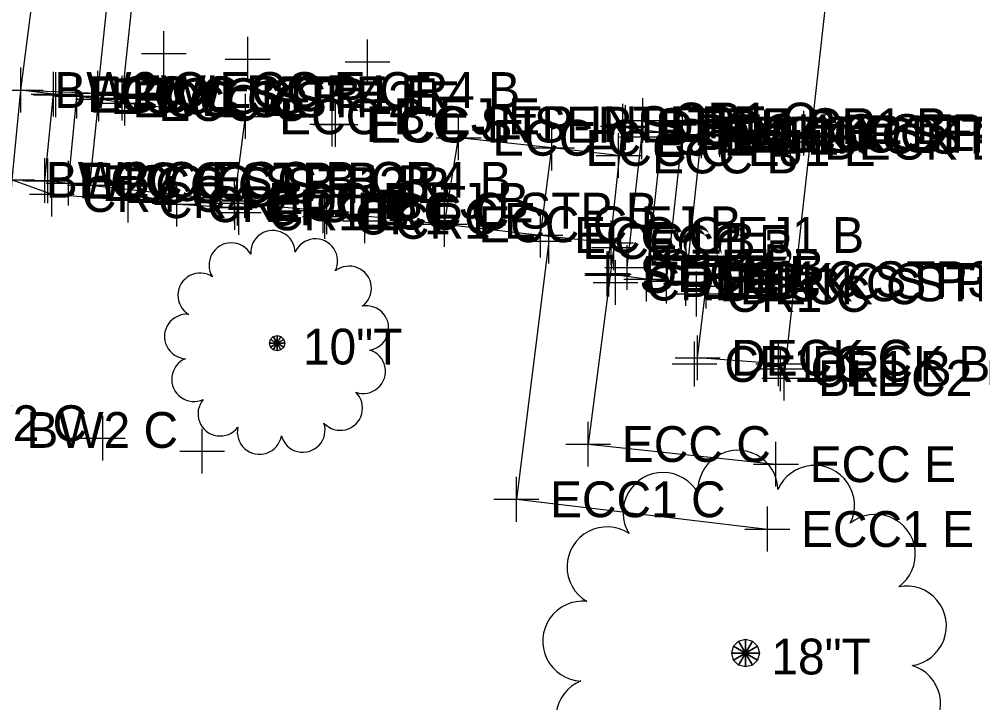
# Model space of a CAD drawing. Extents: x 1363693 to 1365209, y 422201 to 424153.
# Drawn here: x 1364291.51 to 1364334.2, y 423273.43 to 423303.98 of the extents above; entities that cross this region are included whole.
import ezdxf

# ---------------------------------------------------------------- set-up
doc = ezdxf.new("R2010")
doc.units = 0
for name, color, linetype in [('BD_X_Building', 7, 'Continuous'), ('O-ALGN-BASELINE-WERK-CL-RW', 7, 'Continuous'), ('O-ALGN-TEXT-BASELINE-WERK-CL-RW', 7, 'Continuous'), ('OWNERS', 7, 'Continuous'), ('PV_X_Driveway', 7, 'Continuous'), ('PV_X_Joint', 7, 'Continuous'), ('RD_X_Misc_Items', 7, 'Continuous'), ('RD_X_Wall', 7, 'Continuous'), ('SV_X_Original_Ground', 7, 'Continuous'), ('SV_X_Random_Point', 7, 'Continuous'), ('SV_X_Shot_Marker', 7, 'Continuous'), ('VG_X_Cells', 7, 'Continuous'), ('VG_X_Text', 7, 'Continuous')]:
    doc.layers.add(name, color=color, linetype=linetype)

msp = doc.modelspace()

# ---------------------------------------------------------------- linework, layer by layer
at = {"layer": 'BD_X_Building'}
for p, q in [((1364325.684, 423287.942), (1364329.652, 423323.832)), ((1364295.029, 423300.671), (1364295.921, 423309.372)), ((1364296.116, 423300.448), (1364296.997, 423308.883))]:
    msp.add_line(p, q, dxfattribs=at)
at = {"layer": 'O-ALGN-BASELINE-WERK-CL-RW'}
msp.add_line((1364291.58, 423300.813), (1364295.029, 423300.671), dxfattribs=at)
msp.add_lwpolyline([(1364291.2, 423296.798), (1364292.969, 423296.164), (1364296.376, 423295.889), (1364298.558, 423295.71), (1364301.138, 423295.56)], dxfattribs=at)
at = {"layer": 'O-ALGN-TEXT-BASELINE-WERK-CL-RW'}
msp.add_lwpolyline([(1364288.049, 423260.634), (1364290.333, 423285.623), (1364291.2, 423296.798), (1364291.58, 423300.813), (1364292.823, 423310.443), (1364293.111, 423313.713), (1364294.382, 423326.121), (1364294.901, 423331.286), (1364295.277, 423335.321), (1364295.682, 423341.235), (1364297.432, 423360.37), (1364299.6, 423383.973), (1364299.789, 423385.241), (1364300.506, 423393.275), (1364302.133, 423410.038), (1364303.056, 423419.974), (1364303.785, 423425.594), (1364316.813, 423424.472), (1364342.217, 423421.511), (1364361.421, 423419.342)], dxfattribs=at)
at = {"layer": 'OWNERS'}
for p, q in [((1364292.654, 423296.77), (1364293.04, 423300.624)), ((1364293.709, 423296.649), (1364294.082, 423300.539)), ((1364294.665, 423296.563), (1364295.07, 423300.4))]:
    msp.add_line(p, q, dxfattribs=at)
for points in [[(1364301.62, 423299.637), (1364296.233, 423300.231), (1364295.07, 423300.4), (1364294.082, 423300.539), (1364293.154, 423300.605), (1364293.04, 423300.624), (1364291.58, 423300.813)], [(1364291.2, 423296.798), (1364292.654, 423296.77), (1364292.794, 423296.756), (1364293.709, 423296.649), (1364294.665, 423296.563), (1364301.134, 423295.864)]]:
    msp.add_lwpolyline(points, dxfattribs=at)
at = {"layer": 'PV_X_Driveway'}
for p, q in [((1364292.654, 423296.77), (1364293.04, 423300.624)), ((1364293.709, 423296.649), (1364294.082, 423300.539)), ((1364294.665, 423296.563), (1364295.07, 423300.4)), ((1364317.776, 423292.62), (1364318.479, 423299.197)), ((1364318.669, 423292.884), (1364319.322, 423298.718)), ((1364319.523, 423292.359), (1364320.249, 423298.933)), ((1364320.42, 423292.279), (1364321.131, 423298.819)), ((1364321.287, 423292.173), (1364321.979, 423298.769))]:
    msp.add_line(p, q, dxfattribs=at)
for points in [[(1364301.62, 423299.637), (1364296.233, 423300.231), (1364295.07, 423300.4), (1364294.082, 423300.539), (1364293.154, 423300.605), (1364293.04, 423300.624), (1364291.58, 423300.813)], [(1364318.274, 423297.887), (1364315.306, 423298.224), (1364311.139, 423298.678)], [(1364291.2, 423296.798), (1364292.654, 423296.77), (1364292.794, 423296.756), (1364293.709, 423296.649), (1364294.665, 423296.563), (1364301.134, 423295.864)], [(1364301.264, 423295.76), (1364305.092, 423295.423), (1364305.25, 423295.375), (1364310.514, 423294.813), (1364314.788, 423294.332), (1364317.944, 423293.983)], [(1364315.169, 423294.065), (1364313.716, 423282.525), (1364324.927, 423281.197)], [(1364318.074, 423293.771), (1364316.926, 423284.993), (1364325.312, 423284.093)]]:
    msp.add_lwpolyline(points, dxfattribs=at)
at = {"layer": 'PV_X_Joint'}
for p, q in [((1364301.134, 423295.864), (1364301.62, 423299.637)), ((1364310.514, 423294.813), (1364311.139, 423298.678)), ((1364314.788, 423294.332), (1364315.306, 423298.224))]:
    msp.add_line(p, q, dxfattribs=at)
at = {"layer": 'RD_X_Misc_Items'}
for p, q in [((1364318.586, 423299.142), (1364320.249, 423298.933)), ((1364320.249, 423298.933), (1364321.131, 423298.819)), ((1364321.131, 423298.819), (1364321.979, 423298.769)), ((1364321.979, 423298.769), (1364322.808, 423298.825)), ((1364322.808, 423298.825), (1364325.966, 423298.503)), ((1364319.523, 423292.359), (1364317.85, 423292.592)), ((1364320.42, 423292.279), (1364319.523, 423292.359)), ((1364321.287, 423292.173), (1364320.42, 423292.279)), ((1364322.187, 423292.044), (1364321.287, 423292.173)), ((1364321.813, 423288.85), (1364322.187, 423292.044)), ((1364325.419, 423288.579), (1364321.813, 423288.85))]:
    msp.add_line(p, q, dxfattribs=at)
at = {"layer": 'RD_X_Wall'}
for p, q in [((1364295.029, 423300.671), (1364295.921, 423309.372)), ((1364296.116, 423300.448), (1364296.997, 423308.883))]:
    msp.add_line(p, q, dxfattribs=at)
at = {"layer": 'SV_X_Original_Ground'}
for p, q in [((1364297.97, 423301.442), (1364297.97, 423303.442)), ((1364301.717, 423301.192), (1364301.717, 423303.192)), ((1364307.069, 423301.071), (1364307.069, 423303.071)), ((1364296.97, 423302.442), (1364298.97, 423302.442)), ((1364300.717, 423302.192), (1364302.717, 423302.192)), ((1364306.069, 423302.071), (1364308.069, 423302.071)), ((1364319.362, 423298.448), (1364319.362, 423300.448)), ((1364318.586, 423298.142), (1364318.586, 423300.142)), ((1364320.249, 423297.933), (1364320.249, 423299.933)), ((1364321.131, 423297.819), (1364321.131, 423299.819)), ((1364322.808, 423297.825), (1364322.808, 423299.825)), ((1364326.553, 423297.888), (1364326.553, 423299.888)), ((1364318.362, 423299.448), (1364320.362, 423299.448)), ((1364319.322, 423297.718), (1364319.322, 423299.718)), ((1364321.979, 423297.769), (1364321.979, 423299.769)), ((1364325.966, 423297.503), (1364325.966, 423299.503)), ((1364317.586, 423299.142), (1364319.586, 423299.142)), ((1364318.322, 423298.718), (1364320.322, 423298.718)), ((1364319.249, 423298.933), (1364321.249, 423298.933)), ((1364320.131, 423298.819), (1364322.131, 423298.819)), ((1364320.979, 423298.769), (1364322.979, 423298.769)), ((1364321.808, 423298.825), (1364323.808, 423298.825)), ((1364325.553, 423298.888), (1364327.553, 423298.888)), ((1364324.966, 423298.503), (1364326.966, 423298.503)), ((1364292.969, 423295.164), (1364292.969, 423297.164)), ((1364296.376, 423294.889), (1364296.376, 423296.889)), ((1364298.558, 423294.71), (1364298.558, 423296.71)), ((1364301.138, 423294.56), (1364301.138, 423296.56)), ((1364291.969, 423296.164), (1364293.969, 423296.164)), ((1364301.319, 423294.344), (1364301.319, 423296.344)), ((1364305.166, 423294.158), (1364305.166, 423296.158)), ((1364306.95, 423293.964), (1364306.95, 423295.964)), ((1364295.376, 423295.889), (1364297.376, 423295.889)), ((1364297.558, 423295.71), (1364299.558, 423295.71)), ((1364300.138, 423295.56), (1364302.138, 423295.56)), ((1364300.319, 423295.344), (1364302.319, 423295.344)), ((1364304.166, 423295.158), (1364306.166, 423295.158)), ((1364305.95, 423294.964), (1364307.95, 423294.964)), ((1364318.669, 423291.884), (1364318.669, 423293.884)), ((1364317.85, 423291.592), (1364317.85, 423293.592)), ((1364318.141, 423291.209), (1364318.141, 423293.209)), ((1364319.523, 423291.359), (1364319.523, 423293.359)), ((1364320.42, 423291.279), (1364320.42, 423293.279)), ((1364321.287, 423291.173), (1364321.287, 423293.173)), ((1364322.187, 423291.044), (1364322.187, 423293.044)), ((1364316.85, 423292.592), (1364318.85, 423292.592)), ((1364317.669, 423292.884), (1364319.669, 423292.884)), ((1364321.764, 423290.7), (1364321.764, 423292.7)), ((1364317.141, 423292.209), (1364319.141, 423292.209)), ((1364318.523, 423292.359), (1364320.523, 423292.359)), ((1364319.42, 423292.279), (1364321.42, 423292.279)), ((1364320.287, 423292.173), (1364322.287, 423292.173)), ((1364320.764, 423291.7), (1364322.764, 423291.7)), ((1364321.187, 423292.044), (1364323.187, 423292.044)), ((1364321.668, 423287.571), (1364321.668, 423289.571)), ((1364321.813, 423287.85), (1364321.813, 423289.85)), ((1364325.419, 423287.579), (1364325.419, 423289.579)), ((1364325.52, 423287.352), (1364325.52, 423289.352)), ((1364320.813, 423288.85), (1364322.813, 423288.85)), ((1364320.668, 423288.571), (1364322.668, 423288.571)), ((1364324.419, 423288.579), (1364326.419, 423288.579)), ((1364324.52, 423288.352), (1364326.52, 423288.352)), ((1364295.249, 423284.261), (1364295.249, 423286.261)), ((1364299.685, 423283.676), (1364299.685, 423285.676)), ((1364294.249, 423285.261), (1364296.249, 423285.261)), ((1364298.685, 423284.676), (1364300.685, 423284.676))]:
    msp.add_line(p, q, dxfattribs=at)
at = {"layer": 'SV_X_Random_Point'}
for p, q in [((1364295.029, 423299.671), (1364295.029, 423301.671)), ((1364296.116, 423299.448), (1364296.116, 423301.448)), ((1364294.029, 423300.671), (1364296.029, 423300.671)), ((1364295.116, 423300.448), (1364297.116, 423300.448)), ((1364318.479, 423298.197), (1364318.479, 423300.197)), ((1364317.479, 423299.197), (1364319.479, 423299.197)), ((1364317.776, 423291.62), (1364317.776, 423293.62)), ((1364317.78, 423291.545), (1364317.78, 423293.545)), ((1364316.776, 423292.62), (1364318.776, 423292.62)), ((1364316.78, 423292.545), (1364318.78, 423292.545))]:
    msp.add_line(p, q, dxfattribs=at)
at = {"layer": 'SV_X_Shot_Marker'}
for p, q in [((1364291.58, 423299.813), (1364291.58, 423301.813)), ((1364293.04, 423299.624), (1364293.04, 423301.624)), ((1364293.154, 423299.605), (1364293.154, 423301.605)), ((1364294.082, 423299.539), (1364294.082, 423301.539)), ((1364295.07, 423299.4), (1364295.07, 423301.4)), ((1364296.233, 423299.231), (1364296.233, 423301.231)), ((1364290.58, 423300.813), (1364292.58, 423300.813)), ((1364292.04, 423300.624), (1364294.04, 423300.624)), ((1364292.154, 423300.605), (1364294.154, 423300.605)), ((1364293.082, 423300.539), (1364295.082, 423300.539)), ((1364294.07, 423300.4), (1364296.07, 423300.4)), ((1364295.233, 423300.231), (1364297.233, 423300.231)), ((1364301.62, 423298.637), (1364301.62, 423300.637)), ((1364305.493, 423298.289), (1364305.493, 423300.289)), ((1364305.634, 423298.268), (1364305.634, 423300.268)), ((1364300.62, 423299.637), (1364302.62, 423299.637)), ((1364311.139, 423297.678), (1364311.139, 423299.678)), ((1364304.493, 423299.289), (1364306.493, 423299.289)), ((1364304.634, 423299.268), (1364306.634, 423299.268)), ((1364315.306, 423297.224), (1364315.306, 423299.224)), ((1364310.139, 423298.678), (1364312.139, 423298.678)), ((1364318.274, 423296.887), (1364318.274, 423298.887)), ((1364314.306, 423298.224), (1364316.306, 423298.224)), ((1364292.654, 423295.77), (1364292.654, 423297.77)), ((1364292.794, 423295.756), (1364292.794, 423297.756)), ((1364317.274, 423297.887), (1364319.274, 423297.887)), ((1364293.709, 423295.649), (1364293.709, 423297.649)), ((1364294.665, 423295.563), (1364294.665, 423297.563)), ((1364301.134, 423294.864), (1364301.134, 423296.864)), ((1364290.2, 423296.798), (1364292.2, 423296.798)), ((1364291.654, 423296.77), (1364293.654, 423296.77)), ((1364291.794, 423296.756), (1364293.794, 423296.756)), ((1364292.709, 423296.649), (1364294.709, 423296.649)), ((1364293.665, 423296.563), (1364295.665, 423296.563)), ((1364301.264, 423294.76), (1364301.264, 423296.76)), ((1364305.092, 423294.423), (1364305.092, 423296.423)), ((1364305.25, 423294.375), (1364305.25, 423296.375)), ((1364300.134, 423295.864), (1364302.134, 423295.864)), ((1364300.264, 423295.76), (1364302.264, 423295.76)), ((1364310.514, 423293.813), (1364310.514, 423295.813)), ((1364304.092, 423295.423), (1364306.092, 423295.423)), ((1364304.25, 423295.375), (1364306.25, 423295.375)), ((1364314.788, 423293.332), (1364314.788, 423295.332)), ((1364309.514, 423294.813), (1364311.514, 423294.813)), ((1364315.169, 423293.065), (1364315.169, 423295.065)), ((1364317.944, 423292.983), (1364317.944, 423294.983)), ((1364318.074, 423292.771), (1364318.074, 423294.771)), ((1364313.788, 423294.332), (1364315.788, 423294.332)), ((1364314.169, 423294.065), (1364316.169, 423294.065)), ((1364316.944, 423293.983), (1364318.944, 423293.983)), ((1364317.074, 423293.771), (1364319.074, 423293.771)), ((1364325.684, 423286.942), (1364325.684, 423288.942)), ((1364324.684, 423287.942), (1364326.684, 423287.942)), ((1364316.926, 423283.993), (1364316.926, 423285.993)), ((1364315.926, 423284.993), (1364317.926, 423284.993)), ((1364325.312, 423283.093), (1364325.312, 423285.093)), ((1364324.312, 423284.093), (1364326.312, 423284.093)), ((1364313.716, 423281.525), (1364313.716, 423283.525)), ((1364312.716, 423282.525), (1364314.716, 423282.525)), ((1364324.927, 423280.197), (1364324.927, 423282.197)), ((1364323.927, 423281.197), (1364325.927, 423281.197))]:
    msp.add_line(p, q, dxfattribs=at)
at = {"layer": 'VG_X_Cells'}
for points in [[(1364302.732, 423289.672), (1364303.029, 423289.5), (1364303.029, 423289.5), (1364302.686, 423289.5)], [(1364302.857, 423289.797), (1364303.029, 423289.5), (1364303.029, 423289.5), (1364302.732, 423289.672)], [(1364303.029, 423289.843), (1364303.029, 423289.5), (1364303.029, 423289.5), (1364302.857, 423289.797)], [(1364303.201, 423289.797), (1364303.029, 423289.5), (1364303.029, 423289.5), (1364303.029, 423289.843)], [(1364303.326, 423289.672), (1364303.029, 423289.5), (1364303.029, 423289.5), (1364303.201, 423289.797)], [(1364303.372, 423289.5), (1364303.029, 423289.5), (1364303.029, 423289.5), (1364303.326, 423289.672)], [(1364302.686, 423289.5), (1364303.029, 423289.5), (1364303.029, 423289.5), (1364302.732, 423289.328)], [(1364302.732, 423289.328), (1364303.029, 423289.5), (1364303.029, 423289.5), (1364302.857, 423289.203)], [(1364302.857, 423289.203), (1364303.029, 423289.5), (1364303.029, 423289.5), (1364303.029, 423289.157)], [(1364303.029, 423289.157), (1364303.029, 423289.5), (1364303.029, 423289.5), (1364303.201, 423289.203)], [(1364303.201, 423289.203), (1364303.029, 423289.5), (1364303.029, 423289.5), (1364303.326, 423289.328)], [(1364303.326, 423289.328), (1364303.029, 423289.5), (1364303.029, 423289.5), (1364303.372, 423289.5)], [(1364323.416, 423275.959), (1364323.951, 423275.65), (1364323.951, 423275.65), (1364323.333, 423275.65)], [(1364323.642, 423276.185), (1364323.951, 423275.65), (1364323.951, 423275.65), (1364323.416, 423275.959)], [(1364323.951, 423276.268), (1364323.951, 423275.65), (1364323.951, 423275.65), (1364323.642, 423276.185)], [(1364324.26, 423276.185), (1364323.951, 423275.65), (1364323.951, 423275.65), (1364323.951, 423276.268)], [(1364324.486, 423275.959), (1364323.951, 423275.65), (1364323.951, 423275.65), (1364324.26, 423276.185)], [(1364324.569, 423275.65), (1364323.951, 423275.65), (1364323.951, 423275.65), (1364324.486, 423275.959)], [(1364323.333, 423275.65), (1364323.951, 423275.65), (1364323.951, 423275.65), (1364323.416, 423275.341)], [(1364323.416, 423275.341), (1364323.951, 423275.65), (1364323.951, 423275.65), (1364323.642, 423275.115)], [(1364323.642, 423275.115), (1364323.951, 423275.65), (1364323.951, 423275.65), (1364323.951, 423275.032)], [(1364323.951, 423275.032), (1364323.951, 423275.65), (1364323.951, 423275.65), (1364324.26, 423275.115)], [(1364324.26, 423275.115), (1364323.951, 423275.65), (1364323.951, 423275.65), (1364324.486, 423275.341)], [(1364324.486, 423275.341), (1364323.951, 423275.65), (1364323.951, 423275.65), (1364324.569, 423275.65)]]:
    msp.add_lwpolyline(points, close=True, dxfattribs=at)
for centre, radius, start, end in [((1364302.84, 423293.544), 0.992, 1.241, 184.1237), ((1364300.982, 423292.993), 0.992, 28.9333, 211.816), ((1364304.741, 423293.169), 0.992, 333.5487, 156.4314), ((1364299.593, 423291.641), 0.992, 56.6256, 239.5083), ((1364306.25, 423291.953), 0.992, 305.8564, 128.7391), ((1364307.021, 423290.176), 0.992, 278.1641, 101.0468), ((1364298.992, 423289.799), 0.992, 84.3179, 267.2006), ((1364306.877, 423288.243), 0.992, 250.4718, 73.3545), ((1364299.315, 423287.889), 0.992, 112.0103, 294.8929), ((1364300.489, 423286.347), 0.992, 139.7026, 322.5852), ((1364305.853, 423286.599), 0.992, 222.7795, 45.6622), ((1364302.245, 423285.528), 0.992, 167.3949, 350.2776), ((1364304.181, 423285.619), 0.992, 195.0872, 17.9699), ((1364323.61, 423282.929), 1.786, 1.241, 184.1237), ((1364327.032, 423282.254), 1.786, 333.5487, 156.4314), ((1364320.266, 423281.937), 1.786, 28.9333, 211.816), ((1364329.748, 423280.066), 1.786, 305.8564, 128.7391), ((1364317.767, 423279.504), 1.786, 56.6256, 239.5083), ((1364331.136, 423276.866), 1.786, 278.1641, 101.0468), ((1364316.684, 423276.189), 1.786, 84.3179, 267.2006), ((1364330.878, 423273.388), 1.786, 250.4718, 73.3545), ((1364317.266, 423272.75), 1.786, 112.0103, 294.8929)]:
    msp.add_arc(centre, radius, start, end, dxfattribs=at)

# ---------------------------------------------------------------- texts
at = {"layer": 'SV_X_Original_Ground'}
for s, p in [('CR1 C', (1364320.699, 423298.648)), ('DECK B', (1364320.086, 423298.342)), ('STP4 E', (1364320.761, 423297.918)), ('DECK C STP3 E', (1364321.749, 423298.133)), ('DECK C STP2 E', (1364322.631, 423298.019)), ('DECK C STP1 E', (1364323.479, 423297.969)), ('DECK C', (1364324.308, 423298.025)), ('CR1 E', (1364327.89, 423298.088)), ('DECK E', (1364327.466, 423297.703)), ('CR4 C', (1364294.306, 423295.364)), ('CR4 C', (1364297.713, 423295.089)), ('CR4 C', (1364299.895, 423294.91)), ('CR4 E', (1364302.475, 423294.76)), ('CR1 B', (1364302.656, 423294.544)), ('CR1 C', (1364306.503, 423294.358)), ('CR1 E', (1364308.287, 423294.164)), ('DECK E', (1364319.35, 423291.792)), ('STP4 B', (1364320.108, 423292.084)), ('CR1 E', (1364319.478, 423291.409)), ('DECK C STP3 B', (1364321.023, 423291.559)), ('DECK C STP2 B', (1364321.92, 423291.479)), ('DECK C STP1 B', (1364322.787, 423291.373)), ('DECK C', (1364323.687, 423291.244)), ('CR1 C', (1364323.101, 423290.9)), ('DECK C', (1364323.313, 423288.05)), ('CR1 C', (1364323.005, 423287.771)), ('CR1 B', (1364326.857, 423287.552)), ('DECK B', (1364326.919, 423287.779))]:
    msp.add_text(s, height=1.6, dxfattribs=at).set_placement(p)
at = {"layer": 'SV_X_Random_Point'}
for s, p in [('FWL B CR4 E', (1364296.529, 423299.871)), ('TWL B', (1364297.187, 423299.648)), ('STP E CR1 B', (1364319.918, 423298.397)), ('STP B', (1364319.215, 423291.82)), ('STP B', (1364319.219, 423291.745))]:
    msp.add_text(s, height=1.6, dxfattribs=at).set_placement(p)
at = {"layer": 'SV_X_Shot_Marker'}
for s, p in [('BW2 C ECC E CR4 B', (1364293.08, 423300.013)), ('ECC C STP E', (1364294.54, 423299.824)), ('ECC C', (1364294.654, 423299.805)), ('ECC C STP1 E', (1364295.582, 423299.739)), ('ECC C STP2 E', (1364296.57, 423299.6)), ('ECC C', (1364297.733, 423299.431)), ('ECC B EJ E', (1364303.12, 423298.837)), ('ECC STP-INSERT', (1364306.993, 423298.489)), ('ECC-INSERT', (1364307.134, 423298.468)), ('ECC C EJ E', (1364312.639, 423297.878)), ('ECC C EJ1 E', (1364316.806, 423297.424)), ('ECC B', (1364319.774, 423297.087)), ('BW2 C ECC B CR4 B', (1364292.7, 423295.998)), ('ECC C STP B', (1364294.154, 423295.97)), ('ECC C', (1364294.294, 423295.956)), ('ECC C STP1 B', (1364295.209, 423295.849)), ('ECC C STP2 B', (1364296.165, 423295.763)), ('ECC E EJ B', (1364302.634, 423295.064)), ('ECC B', (1364302.764, 423294.96)), ('ECC C STP B', (1364306.592, 423294.623)), ('ECC C', (1364306.75, 423294.575)), ('ECC C EJ B', (1364312.014, 423294.013)), ('ECC C EJ1 B', (1364316.288, 423293.532)), ('ECC1 B', (1364316.669, 423293.265)), ('ECC E', (1364319.444, 423293.183)), ('ECC B', (1364319.574, 423292.971)), ('BLDC2 B', (1364327.184, 423287.142)), ('FW2 C', (1364287.893, 423285.125)), ('BW2 C', (1364291.833, 423284.823)), ('ECC C', (1364318.426, 423284.193)), ('ECC E', (1364326.812, 423283.293)), ('ECC1 C', (1364315.216, 423281.725)), ('ECC1 E', (1364326.427, 423280.397))]:
    msp.add_text(s, height=1.6, dxfattribs=at).set_placement(p)
at = {"layer": 'VG_X_Text'}
for s, p in [('10"T', (1364304.182, 423288.548)), ('18"T', (1364325.104, 423274.698))]:
    msp.add_text(s, height=1.6, dxfattribs=at).set_placement(p)

doc.saveas('drawing.dxf')
